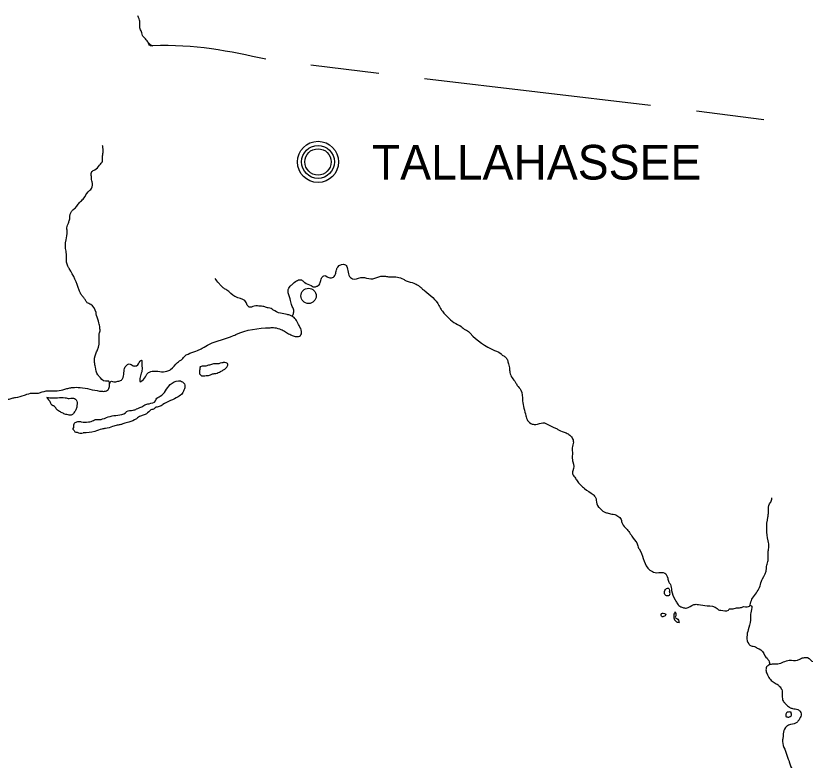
# Model space of a CAD drawing. Extents: x 452225 to 584229, y 1232161 to 1334160.
# Drawn here: x 550729 to 557969, y 1317882 to 1324706 of the extents above; entities that cross this region are included whole.
import ezdxf

# ---------------------------------------------------------------- set-up
doc = ezdxf.new("R2010")
doc.units = 0
doc.layers.add('V-ANNO-SYMB', color=7, linetype='Continuous')

msp = doc.modelspace()

# ---------------------------------------------------------------- linework, layer by layer
at = {"layer": 'V-ANNO-SYMB'}
for p, q in [((554057.9, 1324178.9), (553436.2, 1324252.6)), ((556550.5, 1323882.6), (554476.6, 1324127.9)), ((557590.2, 1323753.8), (556972.6, 1323831.6)), ((553327.9, 1321865.7), (553325.2, 1321868.4))]:
    msp.add_line(p, q, dxfattribs=at)
for centre, radius in [((553500.7, 1323366.9), 188.7), ((553500.7, 1323366.9), 150.9), ((553500.7, 1323366.9), 120.7), ((553414.3, 1322138.4), 70.2)]:
    msp.add_circle(centre, radius, dxfattribs=at)
msp.add_arc((552016.6, 1324515.9), 91.4, 213.18291, 248.62938, dxfattribs=at)
for points in [[(553022.3, 1324307.6), (551986, 1324430.2), (551963.5, 1324432.2), (551941, 1324467), (551908.3, 1324503.9), (551891.9, 1324526.4), (551885.8, 1324548.9), (551869.5, 1324585.7), (551867.4, 1324632.8), (551861.3, 1324677.8), (551849, 1324706.5)], [(551589.1, 1321328.4), (551583.7, 1321355.4), (551551.3, 1321355.4), (551491.9, 1321404), (551481.1, 1321414.8), (551459.5, 1321485), (551451.4, 1321528.2), (551462.2, 1321606.5), (551478.4, 1321644.3), (551494.6, 1321746.9), (551494.6, 1321792.8), (551500, 1321809), (551500, 1321846.8), (551491.9, 1321890), (551470.3, 1321960.2), (551464.9, 1321987.2), (551416.3, 1322060.1), (551383.9, 1322076.3), (551367.7, 1322097.9), (551351.5, 1322124.9), (551340.7, 1322135.7), (551321.8, 1322162.7), (551311, 1322189.7), (551219.2, 1322389.5), (551205.7, 1322411.1), (551194.9, 1322489.4), (551194.9, 1322521.8), (551189.5, 1322548.8), (551189.5, 1322651.4), (551200.3, 1322729.7), (551197.6, 1322751.3), (551208.4, 1322799.9), (551219.2, 1322826.9), (551235.4, 1322905.2), (551251.6, 1322926.8), (551284, 1322953.8), (551294.8, 1322970), (551321.8, 1323002.4), (551354.2, 1323034.8), (551392, 1323091.5), (551424.4, 1323123.9), (551429.8, 1323183.3), (551424.4, 1323204.9), (551421.7, 1323242.7), (551427.1, 1323277.8), (551454.1, 1323294), (551497.3, 1323337.2), (551524.3, 1323375), (551524.3, 1323412.8), (551529.7, 1323453.3), (551529.7, 1323485.7), (551524.3, 1323518.1)], [(550403.8, 1322394.9), (550414.6, 1322335.5), (550360.6, 1322324.7), (550268.8, 1322278.8), (550193.2, 1322278.8), (550166.2, 1322284.2), (550133.8, 1322300.4), (550096, 1322327.4), (550085.2, 1322338.2), (550033.9, 1322403), (549969.1, 1322513.7), (549936.7, 1322546.1), (549920.5, 1322556.9), (549888.1, 1322573.1), (549850.3, 1322600.1), (549815.2, 1322602.8), (549799, 1322613.6), (549782.8, 1322613.6), (549745, 1322619), (549728.8, 1322602.8), (549745, 1322570.4), (549763.9, 1322565), (549790.9, 1322554.2), (549812.5, 1322538), (549855.7, 1322521.8), (549893.5, 1322484), (549904.3, 1322462.4), (549920.5, 1322419.2), (549925.9, 1322397.6), (549931.3, 1322349), (549939.4, 1322327.4), (549944.8, 1322289.6), (549961, 1322243.7), (549977.2, 1322216.7), (550004.2, 1322189.7), (550063.6, 1322162.7), (550144.6, 1322135.7), (550185.1, 1322124.9), (550287.7, 1322079), (550320.1, 1322057.4), (550341.7, 1322046.6), (550384.9, 1322014.2), (550411.9, 1321998), (550433.5, 1321981.8), (550449.7, 1321960.2), (550484.8, 1321925.1), (550501, 1321903.5), (550549.6, 1321806.3), (550565.8, 1321784.7), (550571.2, 1321763.1), (550606.3, 1321660.5), (550617.1, 1321576.8), (550617.1, 1321544.4), (550611.7, 1321517.4), (550611.7, 1321447.2), (550600.9, 1321387.8), (550584.7, 1321352.7), (550541.5, 1321331.1), (550503.7, 1321352.7), (550476.7, 1321379.7), (550444.3, 1321490.4), (550433.5, 1321539), (550433.5, 1321576.8), (550425.4, 1321609.2), (550425.4, 1321636.2), (550420, 1321668.6), (550420, 1321706.4), (550409.2, 1321773.9), (550393, 1321768.5), (550387.6, 1321733.4), (550376.8, 1321701), (550376.8, 1321663.2), (550382.2, 1321620), (550382.2, 1321598.4), (550422.7, 1321449.9), (550422.7, 1321422.9), (550433.5, 1321379.7), (550476.7, 1321282.5), (550506.4, 1321244.7), (550555, 1321196.1), (550592.8, 1321190.7), (550657.6, 1321190.7), (550695.4, 1321201.5), (550727.8, 1321206.9), (550808.8, 1321228.5), (550830.4, 1321236.6), (550900.6, 1321247.4), (550938.4, 1321247.4), (550970.8, 1321258.2), (551046.4, 1321269), (551108.5, 1321269)], [(553265.8, 1321954.8), (553276.6, 1321984.5), (553276.6, 1322016.9), (553260.4, 1322049.3), (553249.6, 1322095.2), (553228, 1322165.4), (553228, 1322197.8), (553255, 1322235.6), (553265.8, 1322246.4), (553303.6, 1322276.1), (553341.4, 1322286.9), (553368.4, 1322270.7), (553379.2, 1322259.9), (553438.6, 1322232.9), (553454.8, 1322222.1), (553476.4, 1322222.1), (553503.4, 1322232.9), (553525, 1322270.7), (553535.8, 1322308.5), (553546.6, 1322319.3), (553562.8, 1322324.7), (553584.4, 1322313.9), (553616.8, 1322303.1), (553649.2, 1322316.6), (553660, 1322338.2), (553670.8, 1322376), (553681.6, 1322403), (553751.8, 1322424.6), (553784.2, 1322327.4), (553816.6, 1322295), (553892.2, 1322305.8), (553927.3, 1322305.8), (554002.9, 1322295), (554040.7, 1322308.5), (554110.9, 1322319.3), (554148.7, 1322313.9), (554170.3, 1322313.9), (554283.7, 1322292.3), (554310.7, 1322276.1), (554380.9, 1322254.5), (554421.4, 1322232.9), (554443, 1322216.7), (554453.8, 1322205.9), (554480.8, 1322184.3), (554610.4, 1322049.3), (554623.9, 1322022.3), (554634.7, 1322006.1), (554661.7, 1321973.7), (554780.5, 1321876.5), (554802.1, 1321865.7), (554842.6, 1321833.3), (554880.4, 1321811.7), (554896.6, 1321795.5), (555120.7, 1321638.9), (555180.1, 1321606.5), (555190.9, 1321595.7), (555217.9, 1321579.5), (555234.1, 1321557.9), (555244.9, 1321525.5), (555255.7, 1321479.6), (555261.1, 1321436.4), (555280, 1321387.8), (555312.4, 1321344.6), (555328.6, 1321317.6), (555361, 1321274.4), (555377.2, 1321177.2), (555406.9, 1321039.5), (555423.1, 1320996.3), (555466.3, 1320963.9), (555498.7, 1320958.5), (555563.5, 1320974.7), (555590.5, 1320969.3), (555663.4, 1320931.5), (555679.6, 1320926.1), (555706.6, 1320909.9), (555776.8, 1320882.9), (555809.2, 1320861.3), (555836.2, 1320828.9), (555841.6, 1320785.7), (555830.8, 1320731.7), (555833.5, 1320704.7), (555833.5, 1320634.5), (555838.9, 1320615.6), (555838.9, 1320534.6), (555833.5, 1320518.4), (555855.1, 1320475.2), (555876.7, 1320442.8), (555944.2, 1320372.6), (556025.2, 1320318.6)], [(553327.9, 1321865.7), (553271.2, 1321946.7), (553249.6, 1321957.5), (553217.2, 1321968.3), (553157.8, 1321979.1), (553087.6, 1322011.5), (553071.4, 1322022.3), (553044.4, 1322027.7), (553012, 1322038.5), (552974.2, 1322043.9), (552914.8, 1322043.9), (552868.9, 1322035.8), (552847.3, 1322062.8), (552841.9, 1322079), (552766.3, 1322122.2), (552739.3, 1322133), (552663.7, 1322192.4), (552636.7, 1322208.6), (552612.4, 1322230.2), (552590.8, 1322254.5), (552558.4, 1322297.7)], [(551589.1, 1321328.4), (551605.3, 1321355.4), (551626.9, 1321350), (551664.7, 1321355.4), (551697.1, 1321366.2), (551713.3, 1321390.5), (551740.3, 1321498.5), (551767.3, 1321514.7), (551805.1, 1321498.5), (551837.5, 1321498.5), (551869.9, 1321539), (551880.7, 1321549.8), (551886.1, 1321512), (551886.1, 1321455.3), (551872.6, 1321406.7), (551867.2, 1321379.7), (551867.2, 1321352.7), (551910.4, 1321385.1), (551937.4, 1321428.3), (551980.6, 1321447.2), (552115.6, 1321447.2), (552148, 1321463.4), (552212.8, 1321528.2), (552229, 1321541.7), (552256, 1321557.9), (552266.8, 1321574.1), (552326.2, 1321611.9), (552396.4, 1321638.9), (552439.6, 1321657.8), (552504.4, 1321695.6), (552725.8, 1321773.9), (552747.4, 1321784.7), (553060.6, 1321846.8), (553103.8, 1321846.8), (553160.5, 1321830.6), (553203.7, 1321809), (553219.9, 1321798.2), (553263.1, 1321776.6), (553300.9, 1321765.8), (553338.7, 1321773.9), (553349.5, 1321811.7), (553327.9, 1321865.7)], [(552420.7, 1321493.1), (552415.3, 1321455.3), (552415.3, 1321422.9), (552431.5, 1321406.7), (552463.9, 1321406.7), (552507.1, 1321412.1), (552534.1, 1321422.9), (552563.8, 1321428.3), (552607, 1321444.5), (552634, 1321460.7), (552671.8, 1321495.8), (552674.5, 1321512), (552631.3, 1321528.2)], [(552420.7, 1321490.4), (552442.3, 1321495.8), (552461.2, 1321495.8), (552474.7, 1321498.5), (552490.9, 1321503.9), (552509.8, 1321506.6), (552544.9, 1321517.4), (552561.1, 1321517.4), (552574.6, 1321520.1), (552593.5, 1321520.1), (552607, 1321525.5), (552631.3, 1321528.2)], [(551108.5, 1321269), (551178.7, 1321282.5), (551216.5, 1321293.3), (551248.9, 1321298.7), (551319.1, 1321298.7), (551497.3, 1321266.3), (551524.3, 1321263.6), (551562.1, 1321269), (551583.7, 1321290.6), (551589.1, 1321328.4)], [(551329.9, 1320982.8), (551394.7, 1320982.8), (551421.7, 1320988.2), (551459.5, 1321004.4), (551497.3, 1321004.4), (551524.3, 1321009.8), (551594.5, 1321034.1), (551664.7, 1321044.9), (551734.9, 1321066.5), (551745.7, 1321077.3), (551805.1, 1321090.8), (551837.5, 1321101.6), (551859.1, 1321112.4), (551875.3, 1321117.8), (551913.1, 1321139.4), (551950.9, 1321150.2), (552010.3, 1321177.2), (552015.7, 1321190.7), (552053.5, 1321217.7), (552145.3, 1321325.7), (552220.9, 1321360.8), (552258.7, 1321350), (552280.3, 1321306.8), (552274.9, 1321285.2), (552256, 1321244.7), (552218.2, 1321212.3), (552077.8, 1321142.1), (552045.4, 1321123.2), (552007.6, 1321112.4), (551996.8, 1321101.6), (551975.2, 1321096.2), (551948.2, 1321074.6), (551905, 1321047.6), (551872.6, 1321036.8), (551834.8, 1321012.5), (551764.6, 1320980.1), (551718.7, 1320969.3), (551691.7, 1320958.5), (551659.3, 1320953.1), (551616.1, 1320939.6), (551551.3, 1320923.4), (551518.9, 1320918), (551454.1, 1320896.4), (551346.1, 1320882.9)], [(551014, 1321209.6), (551041, 1321204.2), (551181.4, 1321204.2), (551219.2, 1321198.8), (551246.2, 1321201.5), (551284, 1321185.3), (551289.4, 1321134), (551284, 1321101.6), (551267.8, 1321074.6), (551243.5, 1321047.6), (551208.4, 1321047.6), (551170.6, 1321058.4), (551138.2, 1321074.6), (551105.8, 1321096.2), (551095, 1321112.4), (551068, 1321134)], [(551014, 1321209.6), (551022.1, 1321193.4), (551035.6, 1321179.9), (551051.8, 1321147.5), (551068, 1321134)], [(551329.9, 1320982.8), (551294.8, 1320982.8), (551278.6, 1320977.4), (551265.1, 1320969.3), (551259.7, 1320953.1), (551257, 1320931.5), (551251.6, 1320915.3), (551265.1, 1320904.5), (551270.5, 1320891), (551292.1, 1320888.3), (551305.6, 1320882.9), (551346.1, 1320882.9)], [(556025.2, 1320318.6), (556036, 1320302.4), (556046.8, 1320291.6), (556052.2, 1320264.6), (556073.8, 1320202.5), (556084.6, 1320191.7), (556125.1, 1320159.3), (556152.1, 1320148.5), (556195.3, 1320137.7), (556222.3, 1320135), (556260.1, 1320113.4), (556276.3, 1320097.2), (556287.1, 1320062.1), (556319.5, 1320013.5), (556335.7, 1319997.3), (556392.4, 1319916.3), (556430.2, 1319856.9), (556435.6, 1319835.3), (556446.4, 1319819.1), (556524.7, 1319643.6), (556535.5, 1319632.8), (556578.7, 1319605.8), (556605.7, 1319600.4), (556681.3, 1319597.7), (556708.3, 1319551.8), (556719.1, 1319514), (556732.6, 1319492.4), (556743.4, 1319438.4), (556775.8, 1319352), (556792, 1319325), (556819, 1319292.6), (556846, 1319281.8), (556878.4, 1319276.4), (556948.6, 1319308.8), (556989.1, 1319308.8), (557070.1, 1319298), (557161.9, 1319271), (557172.7, 1319260.2), (557194.3, 1319257.5), (557264.5, 1319257.5), (557275.3, 1319268.3), (557296.9, 1319268.3), (557340.1, 1319279.1), (557367.1, 1319279.1), (557404.9, 1319289.9)], [(557404.9, 1319289.9), (557458.9, 1319295.3), (557475.1, 1319346.6), (557485.9, 1319368.2), (557550.7, 1319465.4), (557566.9, 1319522.1), (557577.7, 1319543.7), (557615.5, 1319640.9), (557615.5, 1319657.1), (557626.3, 1319703), (557629, 1319724.6), (557629, 1319789.4), (557634.4, 1319827.2), (557634.4, 1319865), (557629, 1319892), (557626.3, 1320110.7), (557631.7, 1320143.1), (557631.7, 1320170.1), (557642.5, 1320232.2), (557653.3, 1320248.4), (557664.1, 1320286.2)], [(556681.3, 1319400.6), (556681.3, 1319438.4), (556713.7, 1319460), (556724.5, 1319427.6)], [(556681.3, 1319400.6), (556694.8, 1319392.5), (556711, 1319392.5), (556724.5, 1319395.2), (556729.9, 1319408.7), (556724.5, 1319427.6)], [(557467, 1319300.7), (557469.7, 1319300.7), (557472.4, 1319246.7), (557467, 1319219.7), (557467, 1319165.7), (557445.4, 1319076.6), (557434.6, 1319011.8), (557450.8, 1318947), (557472.4, 1318930.8), (557512.9, 1318920), (557529.1, 1318909.2), (557545.3, 1318903.8), (557599.3, 1318839)], [(556689.4, 1319219.7), (556684, 1319206.2), (556670.5, 1319198.1), (556657, 1319195.4), (556648.9, 1319208.9), (556651.6, 1319225.1)], [(556651.6, 1319225.1), (556667.8, 1319230.5), (556689.4, 1319219.7)], [(556775.8, 1319241.3), (556765, 1319219.7), (556765, 1319187.3), (556781.2, 1319154.9), (556813.6, 1319144.1)], [(556775.8, 1319241.3), (556781.2, 1319227.8), (556783.9, 1319214.3), (556778.5, 1319187.3), (556792, 1319181.9), (556813.6, 1319144.1)], [(557639.8, 1318758), (557647.9, 1318760.7), (557691.1, 1318766.1), (557718.1, 1318766.1), (557823.4, 1318798.5), (557899, 1318798.5), (557926, 1318812), (557963.8, 1318822.8), (557990.8, 1318822.8), (558044.8, 1318785), (558066.4, 1318790.4), (558098.8, 1318833.6), (558142, 1318855.2), (558174.4, 1318849.8), (558206.8, 1318833.6)], [(557599.3, 1318839), (557637.1, 1318758), (557615.5, 1318736.4), (557610.1, 1318701.3), (557623.6, 1318663.5), (557650.6, 1318620.3), (557683, 1318593.3), (557720.8, 1318571.7), (557731.6, 1318560.9), (557753.2, 1318528.5), (557758.6, 1318485.3), (557758.6, 1318458.3), (557769.4, 1318420.5), (557788.3, 1318398.9), (557826.1, 1318366.5), (557853.1, 1318355.7), (557901.7, 1318344.9), (557923.3, 1318328.7), (557928.7, 1318282.8), (557917.9, 1318261.2), (557907.1, 1318245), (557885.5, 1318223.4), (557815.3, 1318201.8), (557788.3, 1318180.2), (557766.7, 1318123.5), (557766.7, 1318101.9), (557761.3, 1318069.5), (557801.8, 1317929.1), (557812.6, 1317891.3), (557823.4, 1317867), (557834.2, 1317829.2), (557850.4, 1317791.4), (557858.5, 1317694.2), (557858.5, 1317651), (557853.1, 1317610.5), (557853.1, 1317572.7), (557847.7, 1317556.5), (557847.7, 1317529.5), (557842.3, 1317502.5), (557842.3, 1317480.9), (557834.2, 1317235.2), (557828.8, 1317197.4), (557812.6, 1317170.4), (557753.2, 1317097.5), (557747.8, 1317070.5), (557742.4, 1317054.3), (557739.7, 1316922), (557707.3, 1316851.8), (557701.9, 1316819.4), (557669.5, 1316746.5), (557631.7, 1316633.1), (557615.5, 1316600.7), (557604.7, 1316584.5), (557596.6, 1316560.2), (557537.2, 1316473.8), (557526.4, 1316452.2), (557504.8, 1316419.8), (557483.2, 1316357.7), (557467, 1316330.7), (557440, 1316255.1), (557429.2, 1316217.3), (557407.6, 1316187.6), (557396.8, 1316166), (557396.8, 1316122.8), (557404.9, 1316101.2), (557410.3, 1316079.6), (557410.3, 1316052.6), (557415.7, 1316009.4), (557415.7, 1315982.4), (557394.1, 1315866.3), (557394.1, 1315828.5), (557388.7, 1315796.1), (557391.4, 1315723.2), (557386, 1315690.8), (557386, 1315663.8), (557380.6, 1315620.6), (557380.6, 1315599), (557350.9, 1315380.3), (557313.1, 1315275), (557275.3, 1315210.2), (557264.5, 1315172.4), (557264.5, 1315113), (557286.1, 1315061.7), (557296.9, 1315050.9), (557321.2, 1314996.9), (557337.4, 1314969.9), (557407.6, 1314986.1), (557445.4, 1314978), (557467, 1314915.9), (557477.8, 1314899.7), (557494, 1314856.5)], [(557839.6, 1318320.6), (557804.5, 1318320.6), (557793.7, 1318309.8), (557791, 1318296.3), (557791, 1318282.8)], [(557791, 1318282.8), (557818, 1318277.4), (557839.6, 1318288.2), (557839.6, 1318320.6)]]:
    msp.add_spline(points, degree=3, dxfattribs=at)

# ---------------------------------------------------------------- texts
msp.add_text('TALLAHASSEE', height=317.52, rotation=0, dxfattribs=at).set_placement((553994.9, 1323205.4))

doc.saveas('drawing.dxf')
